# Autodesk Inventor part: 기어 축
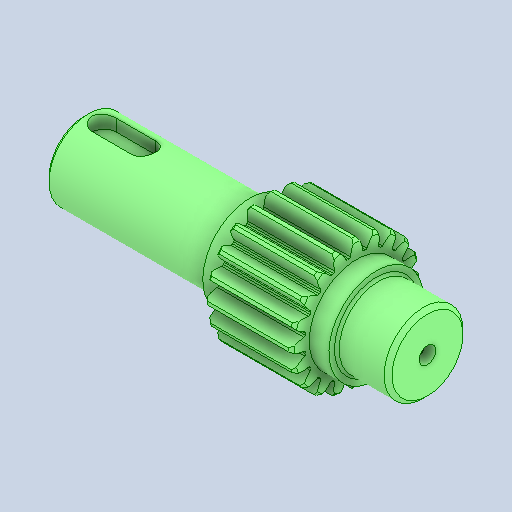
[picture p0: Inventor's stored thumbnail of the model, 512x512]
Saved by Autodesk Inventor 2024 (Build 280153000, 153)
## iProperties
Created: 2025-11
Part Number: 기어 축
Material: 강철, 합금
Document SubType Name: Modeling
Designer: Edu07
Density: 7.73 g/cm^3
Appearance: 기본값
Author: jhkim
Sending System: Autodesk Inventor 2026
Preprocessor: ST-DEVELOPER v20.1
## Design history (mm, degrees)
node "기어 축1"
node "솔리드2"
node "솔리드1"
